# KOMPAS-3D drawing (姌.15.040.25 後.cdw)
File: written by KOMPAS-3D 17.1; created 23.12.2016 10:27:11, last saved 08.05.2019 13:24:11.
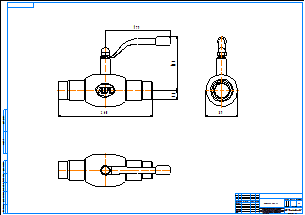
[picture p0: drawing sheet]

Sheet 1: A1, landscape

Title block, sheet 1: name: КШ.15.040.25 сс; material: Внимание! Данный продукт является объектом авторского права ООО «Торговый Дом АДЛ». / Запрещается изменение, копирование, распространение / (в том числе путем копирования на другие сайты и ресурсы в Интернете) / или любое иное использование информации и объектов без предварительного / согласия правообладателя (ООО «Торговый Дом АДЛ»).; sheets: 1; organisation: ООО "Торговый дом АДЛ"; sheet format: A1; stored path: C:\Users\tra\Desktop\2д чертежи\Шаровые краны БИВАЛ\КШ_Бивал_серия_14_15\KOMPAS_2D\КШ.15.040.25 сс.cdw

Views: Вид 1, Проекционный вид 2, Проекционный вид 3
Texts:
  Klimkovich
  ADL
Dimensions and other numbers on the sheet: 260; 179; 148; 24; 89; 1:1; 1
